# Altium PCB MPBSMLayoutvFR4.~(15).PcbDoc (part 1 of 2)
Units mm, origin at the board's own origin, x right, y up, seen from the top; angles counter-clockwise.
Board outline 131.7 x 110.39 mm, 4 copper layers (Top Layer, Power, GroundPlane, Bottom Layer), stack 2.286 mm thick; 156 components, 77 nets, 429 pads, 117 vias.
Unrouted connection lines stored in the file: 44.
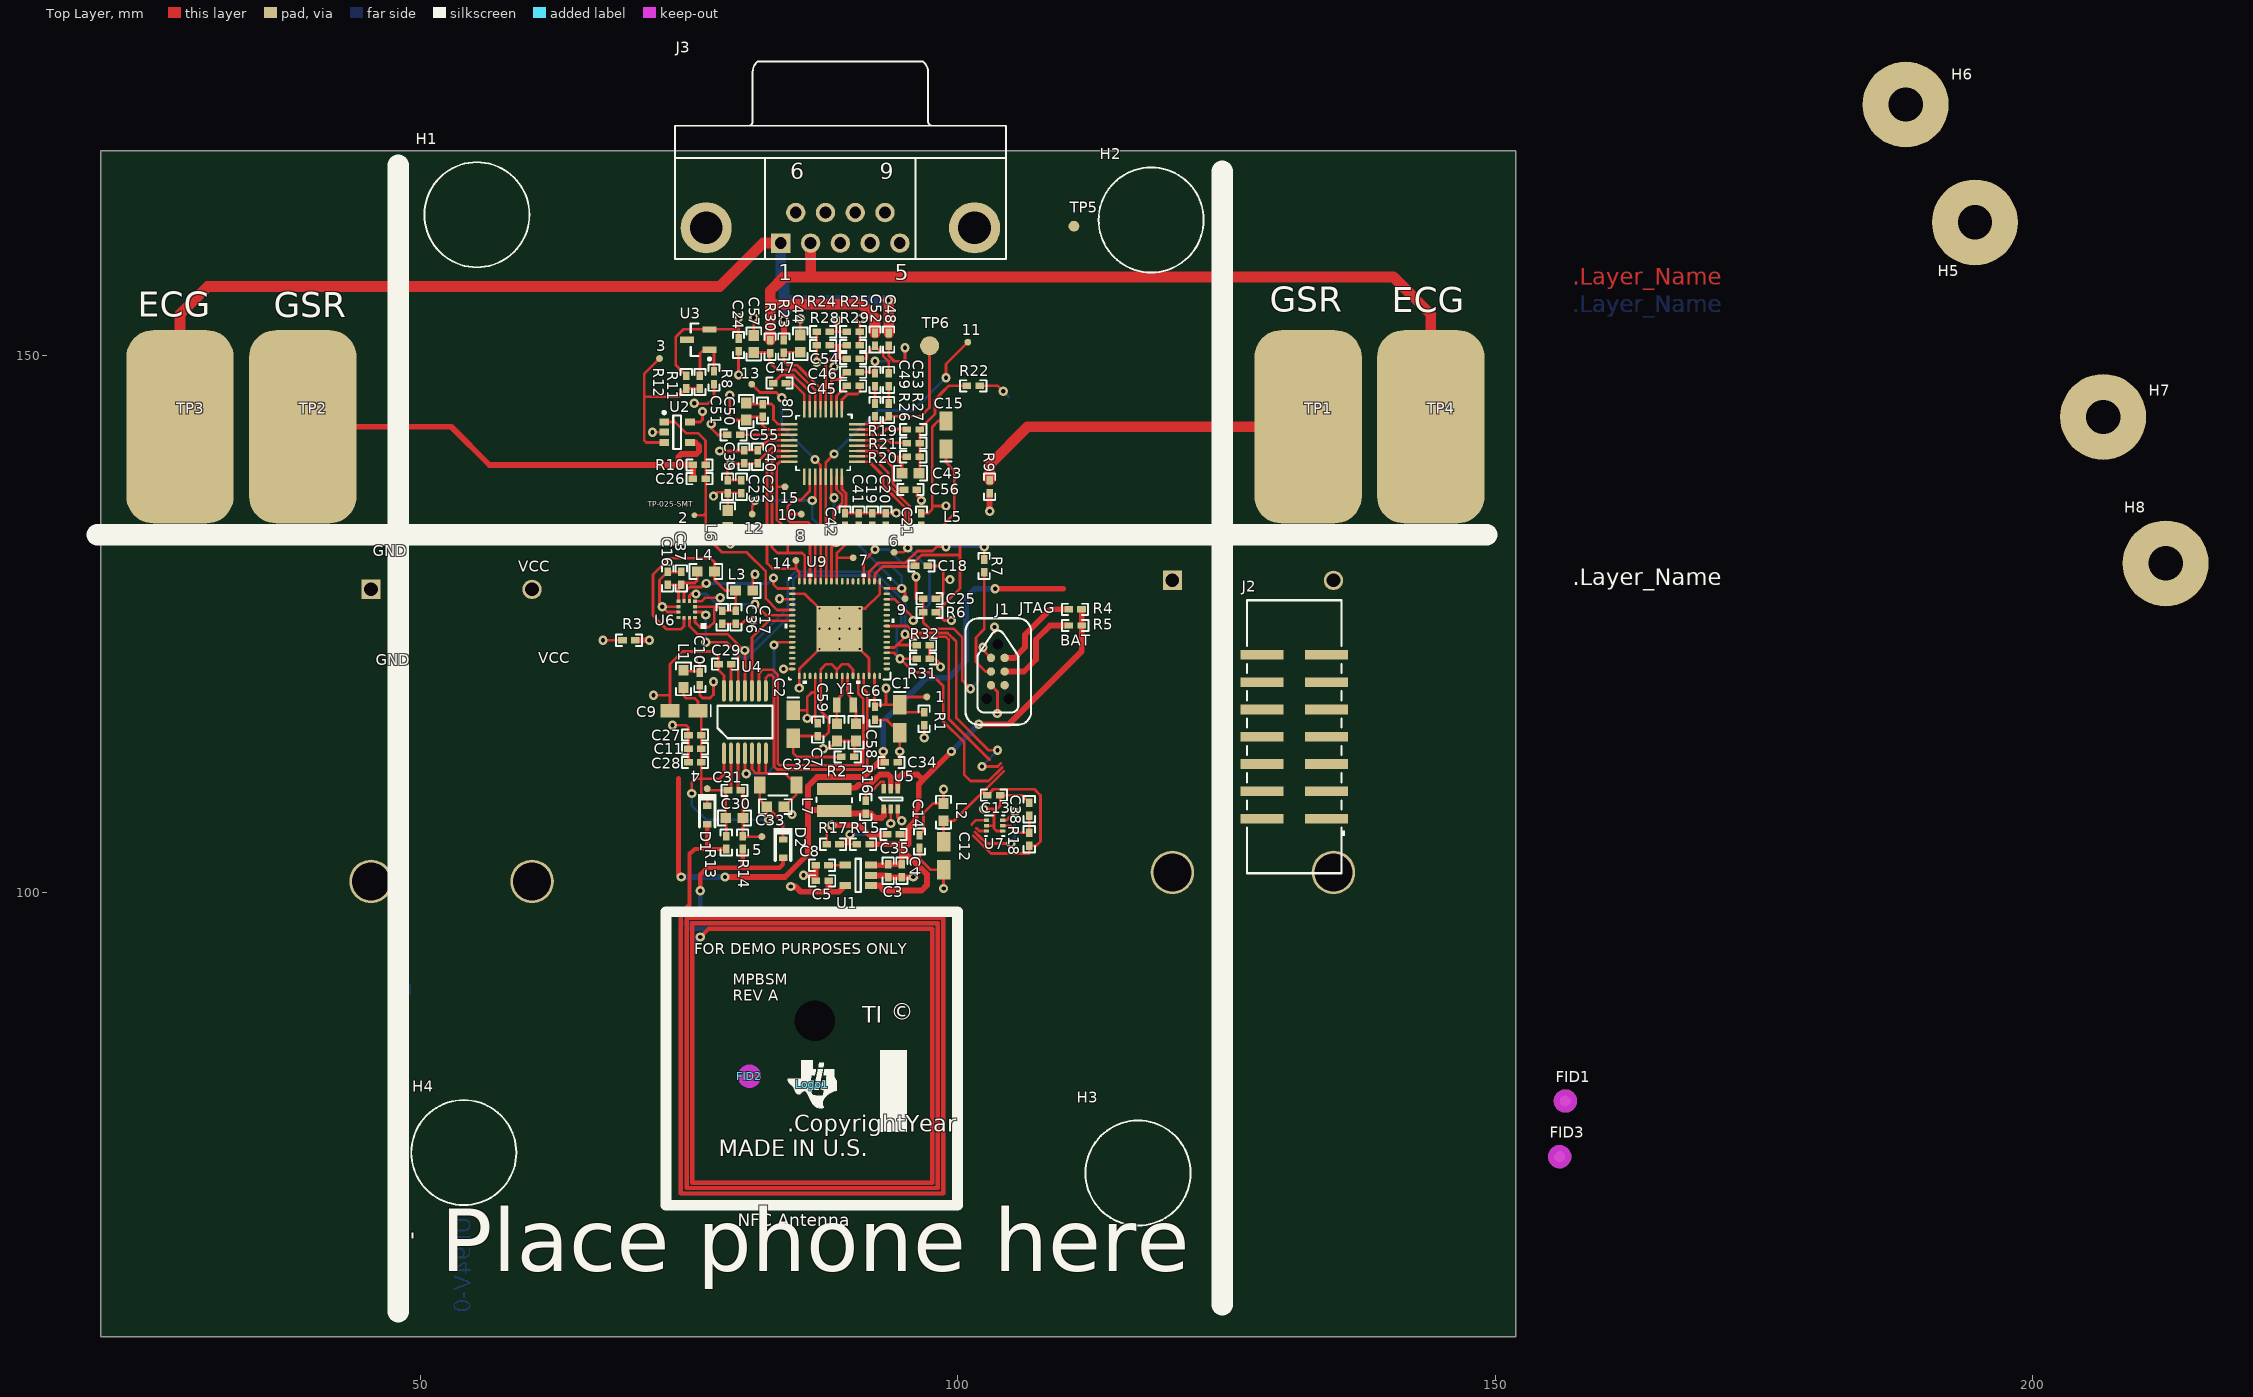
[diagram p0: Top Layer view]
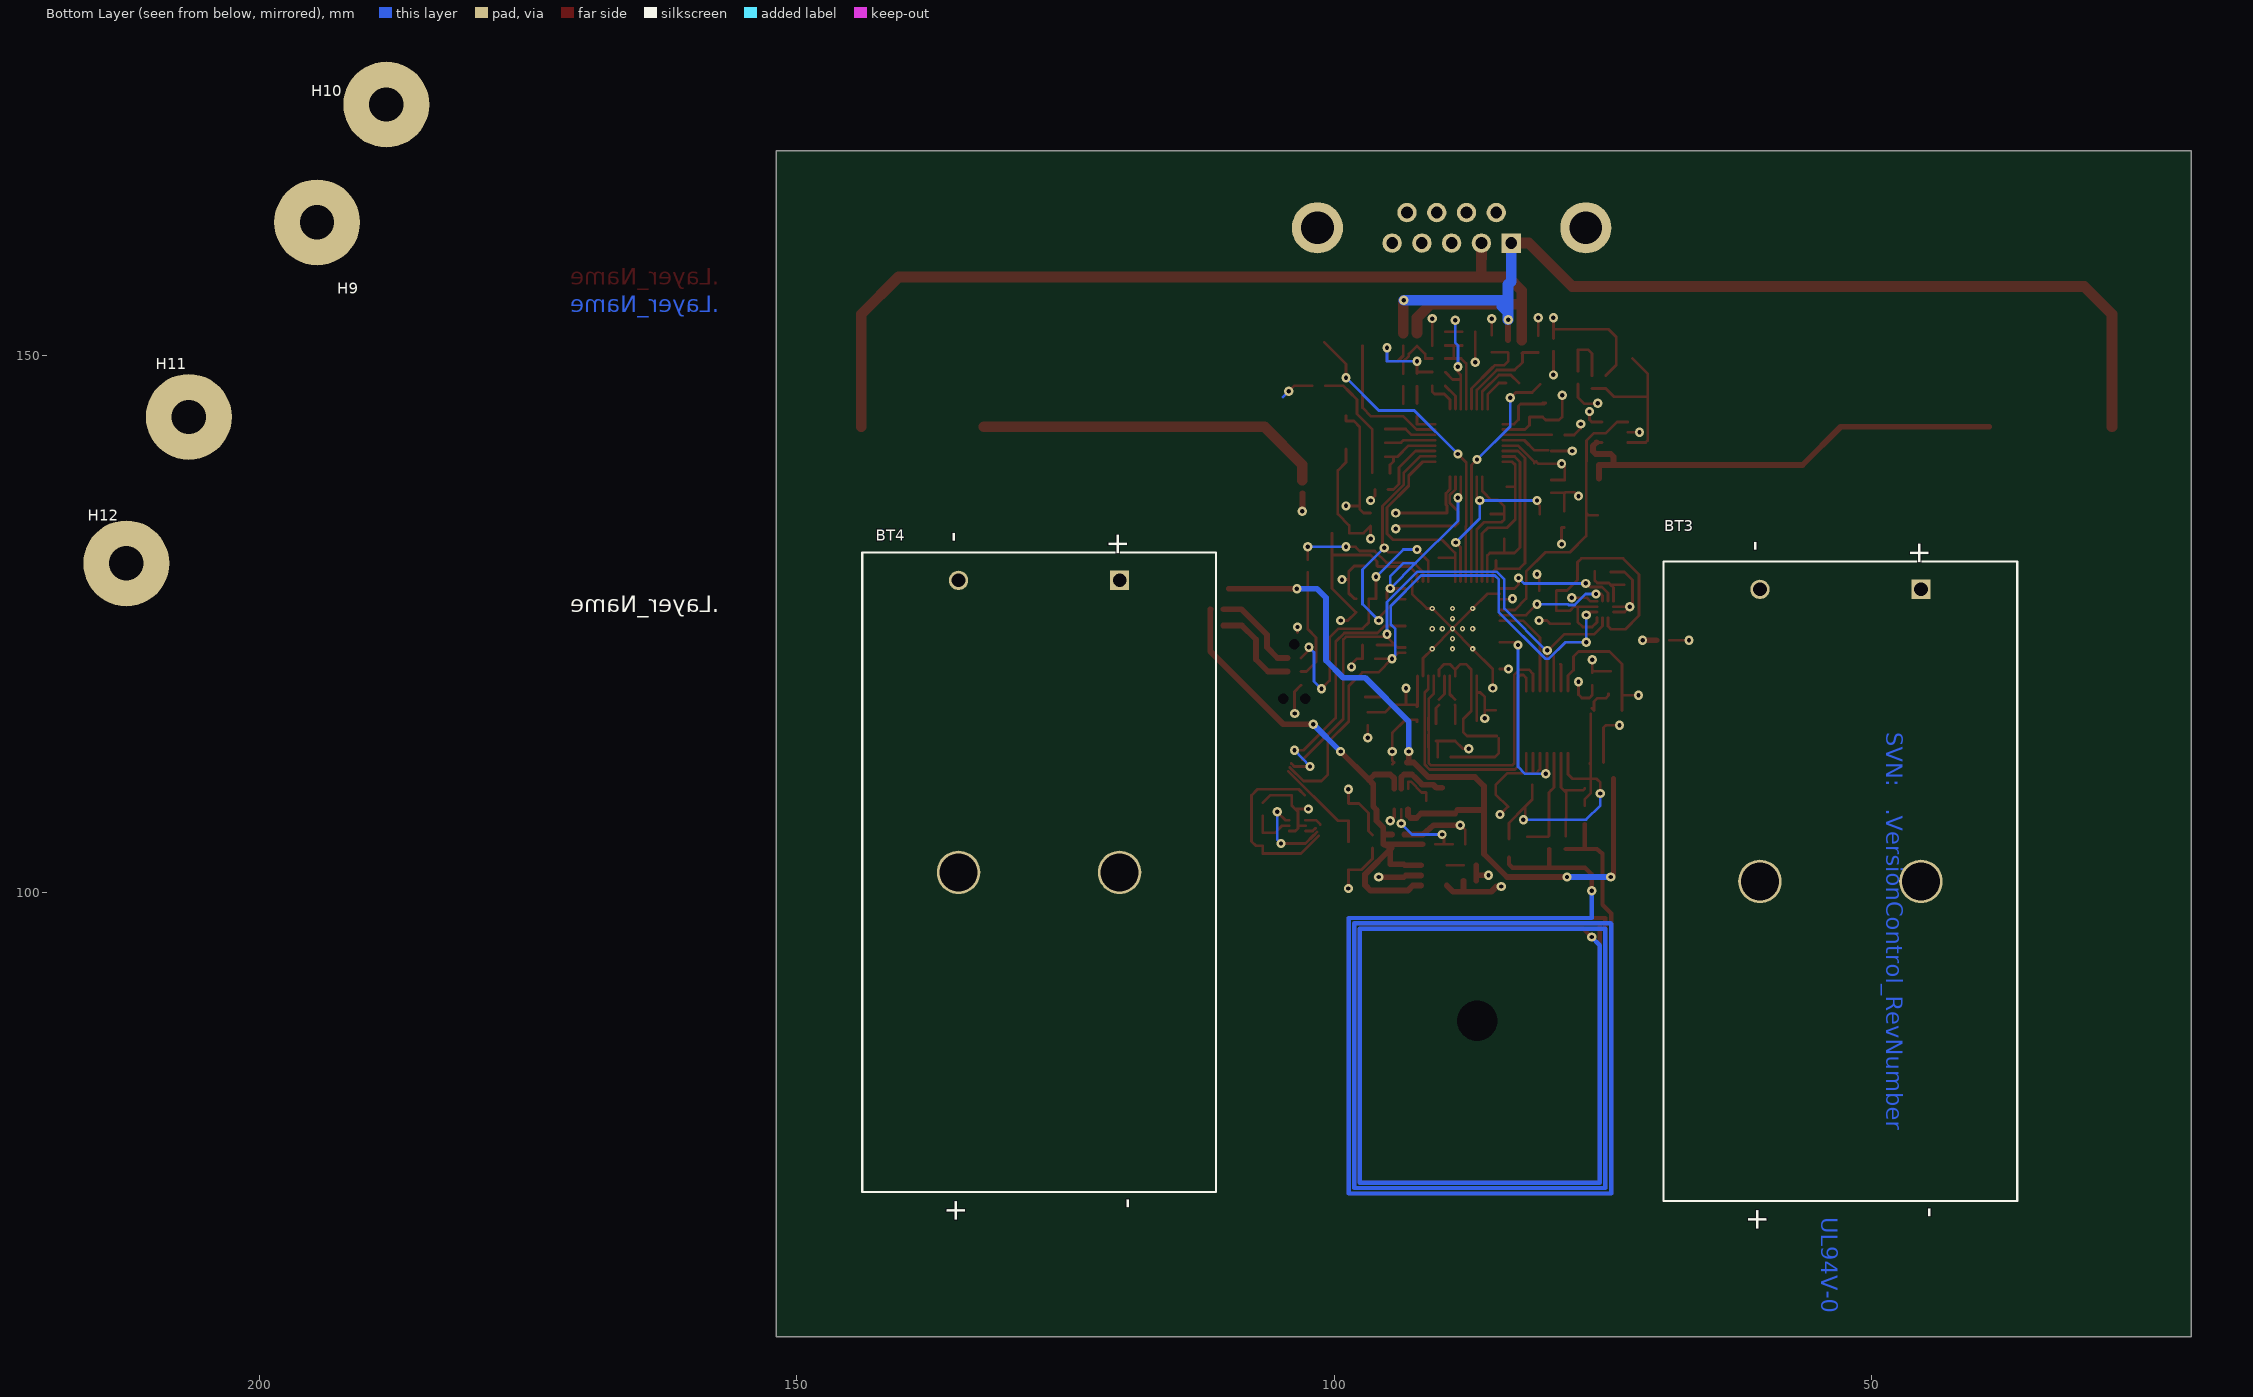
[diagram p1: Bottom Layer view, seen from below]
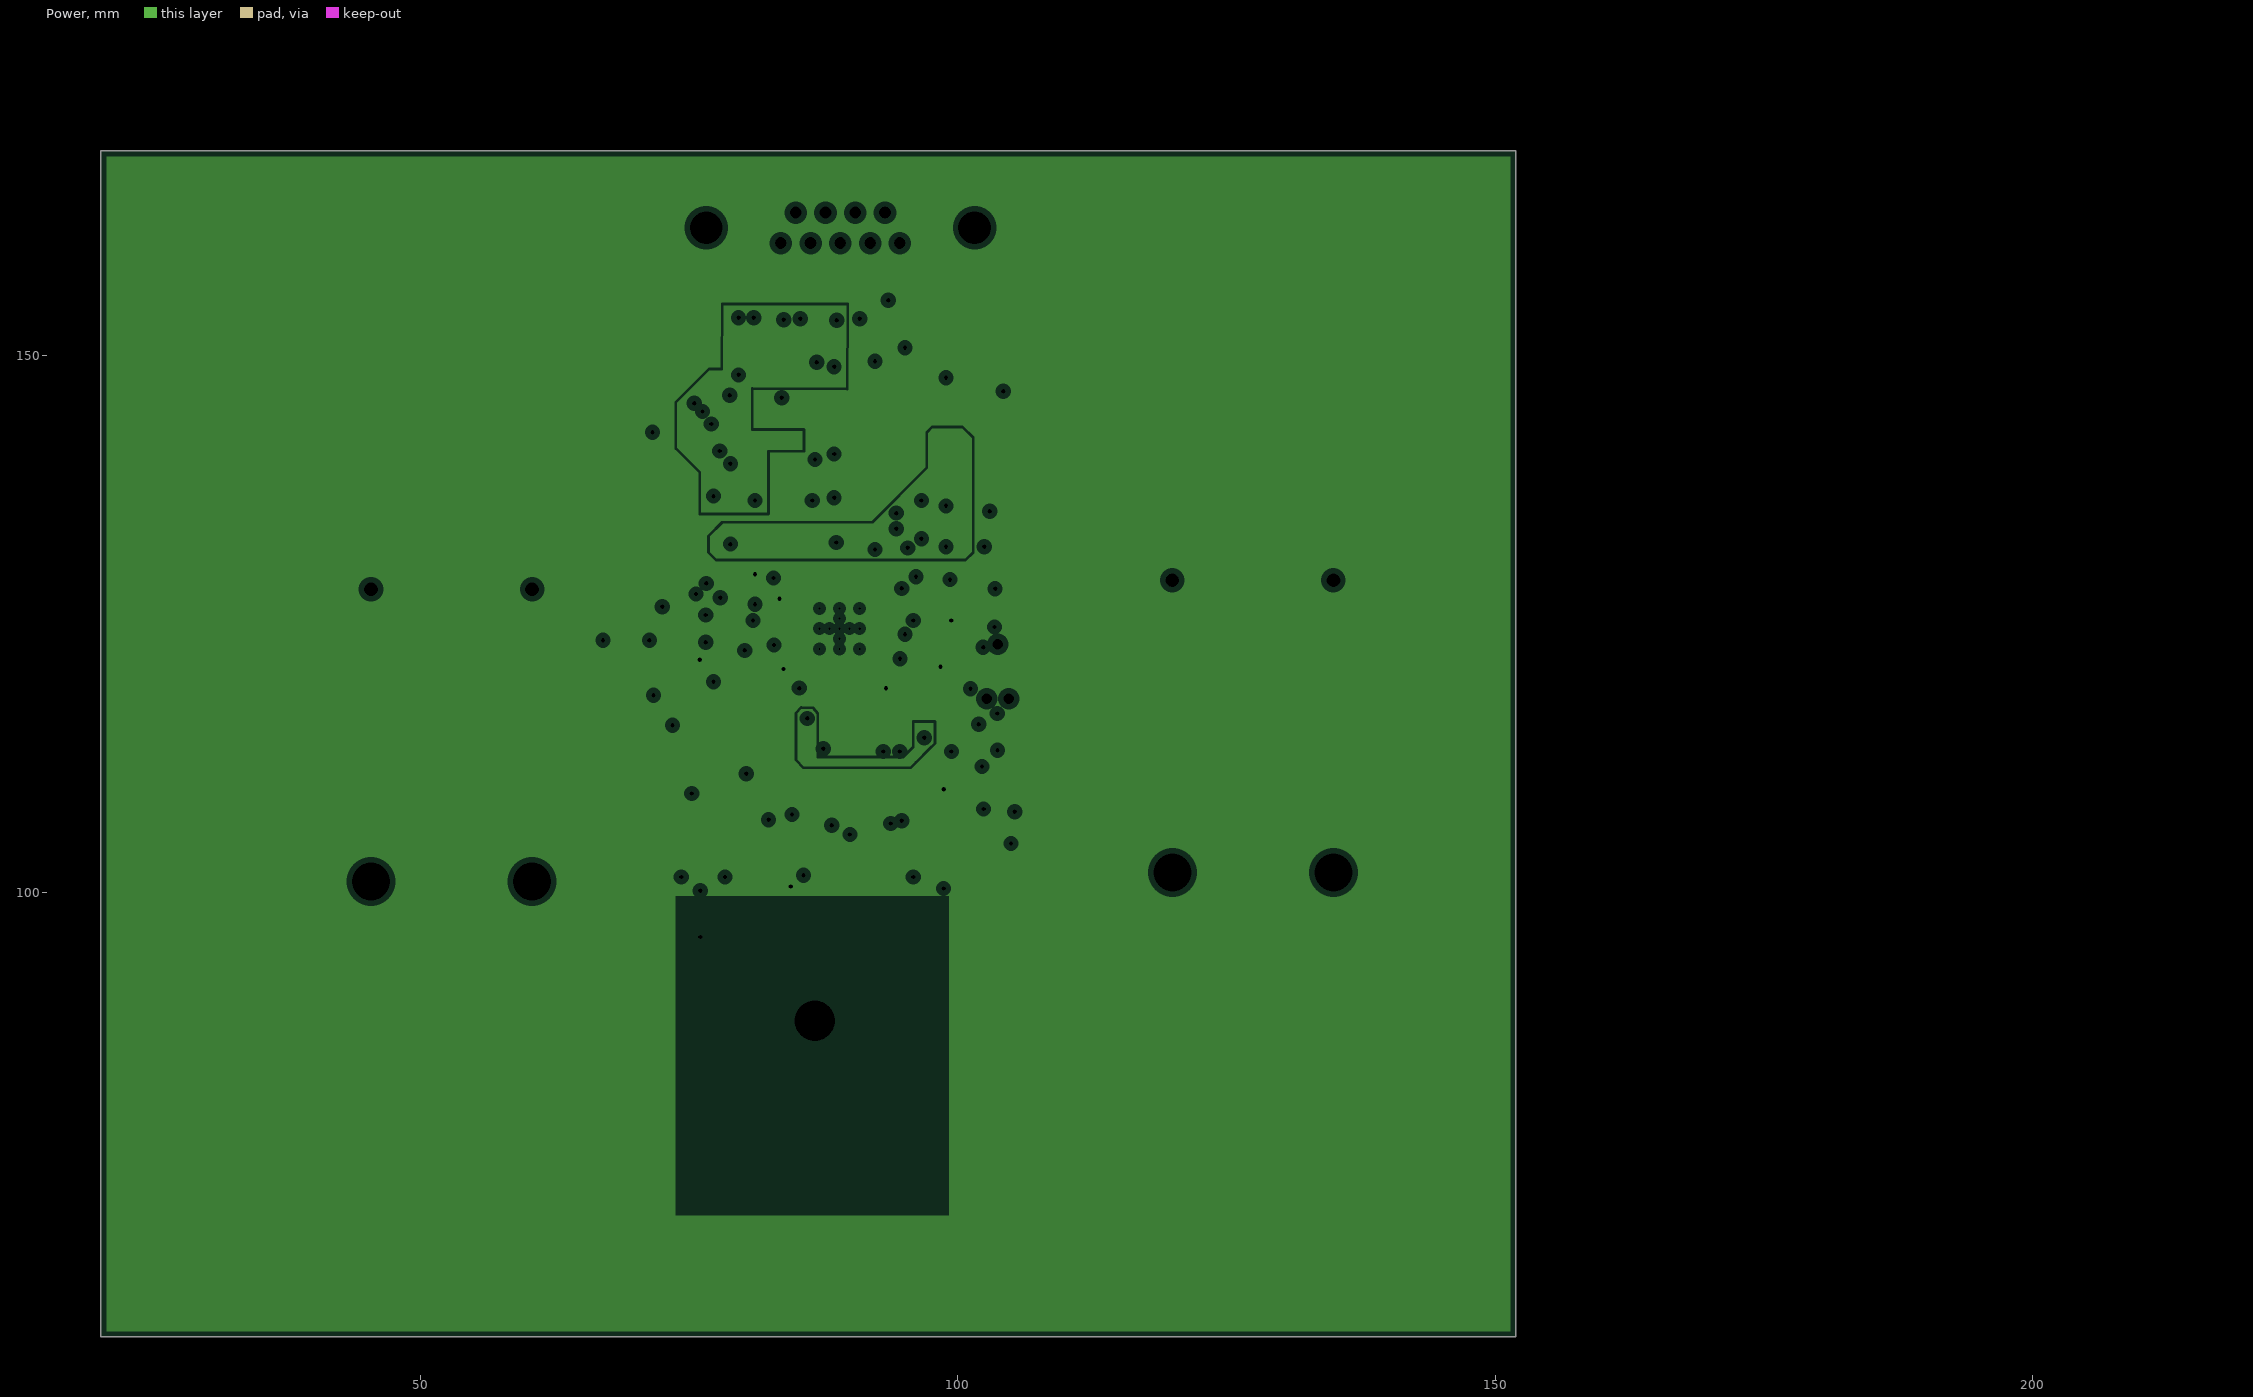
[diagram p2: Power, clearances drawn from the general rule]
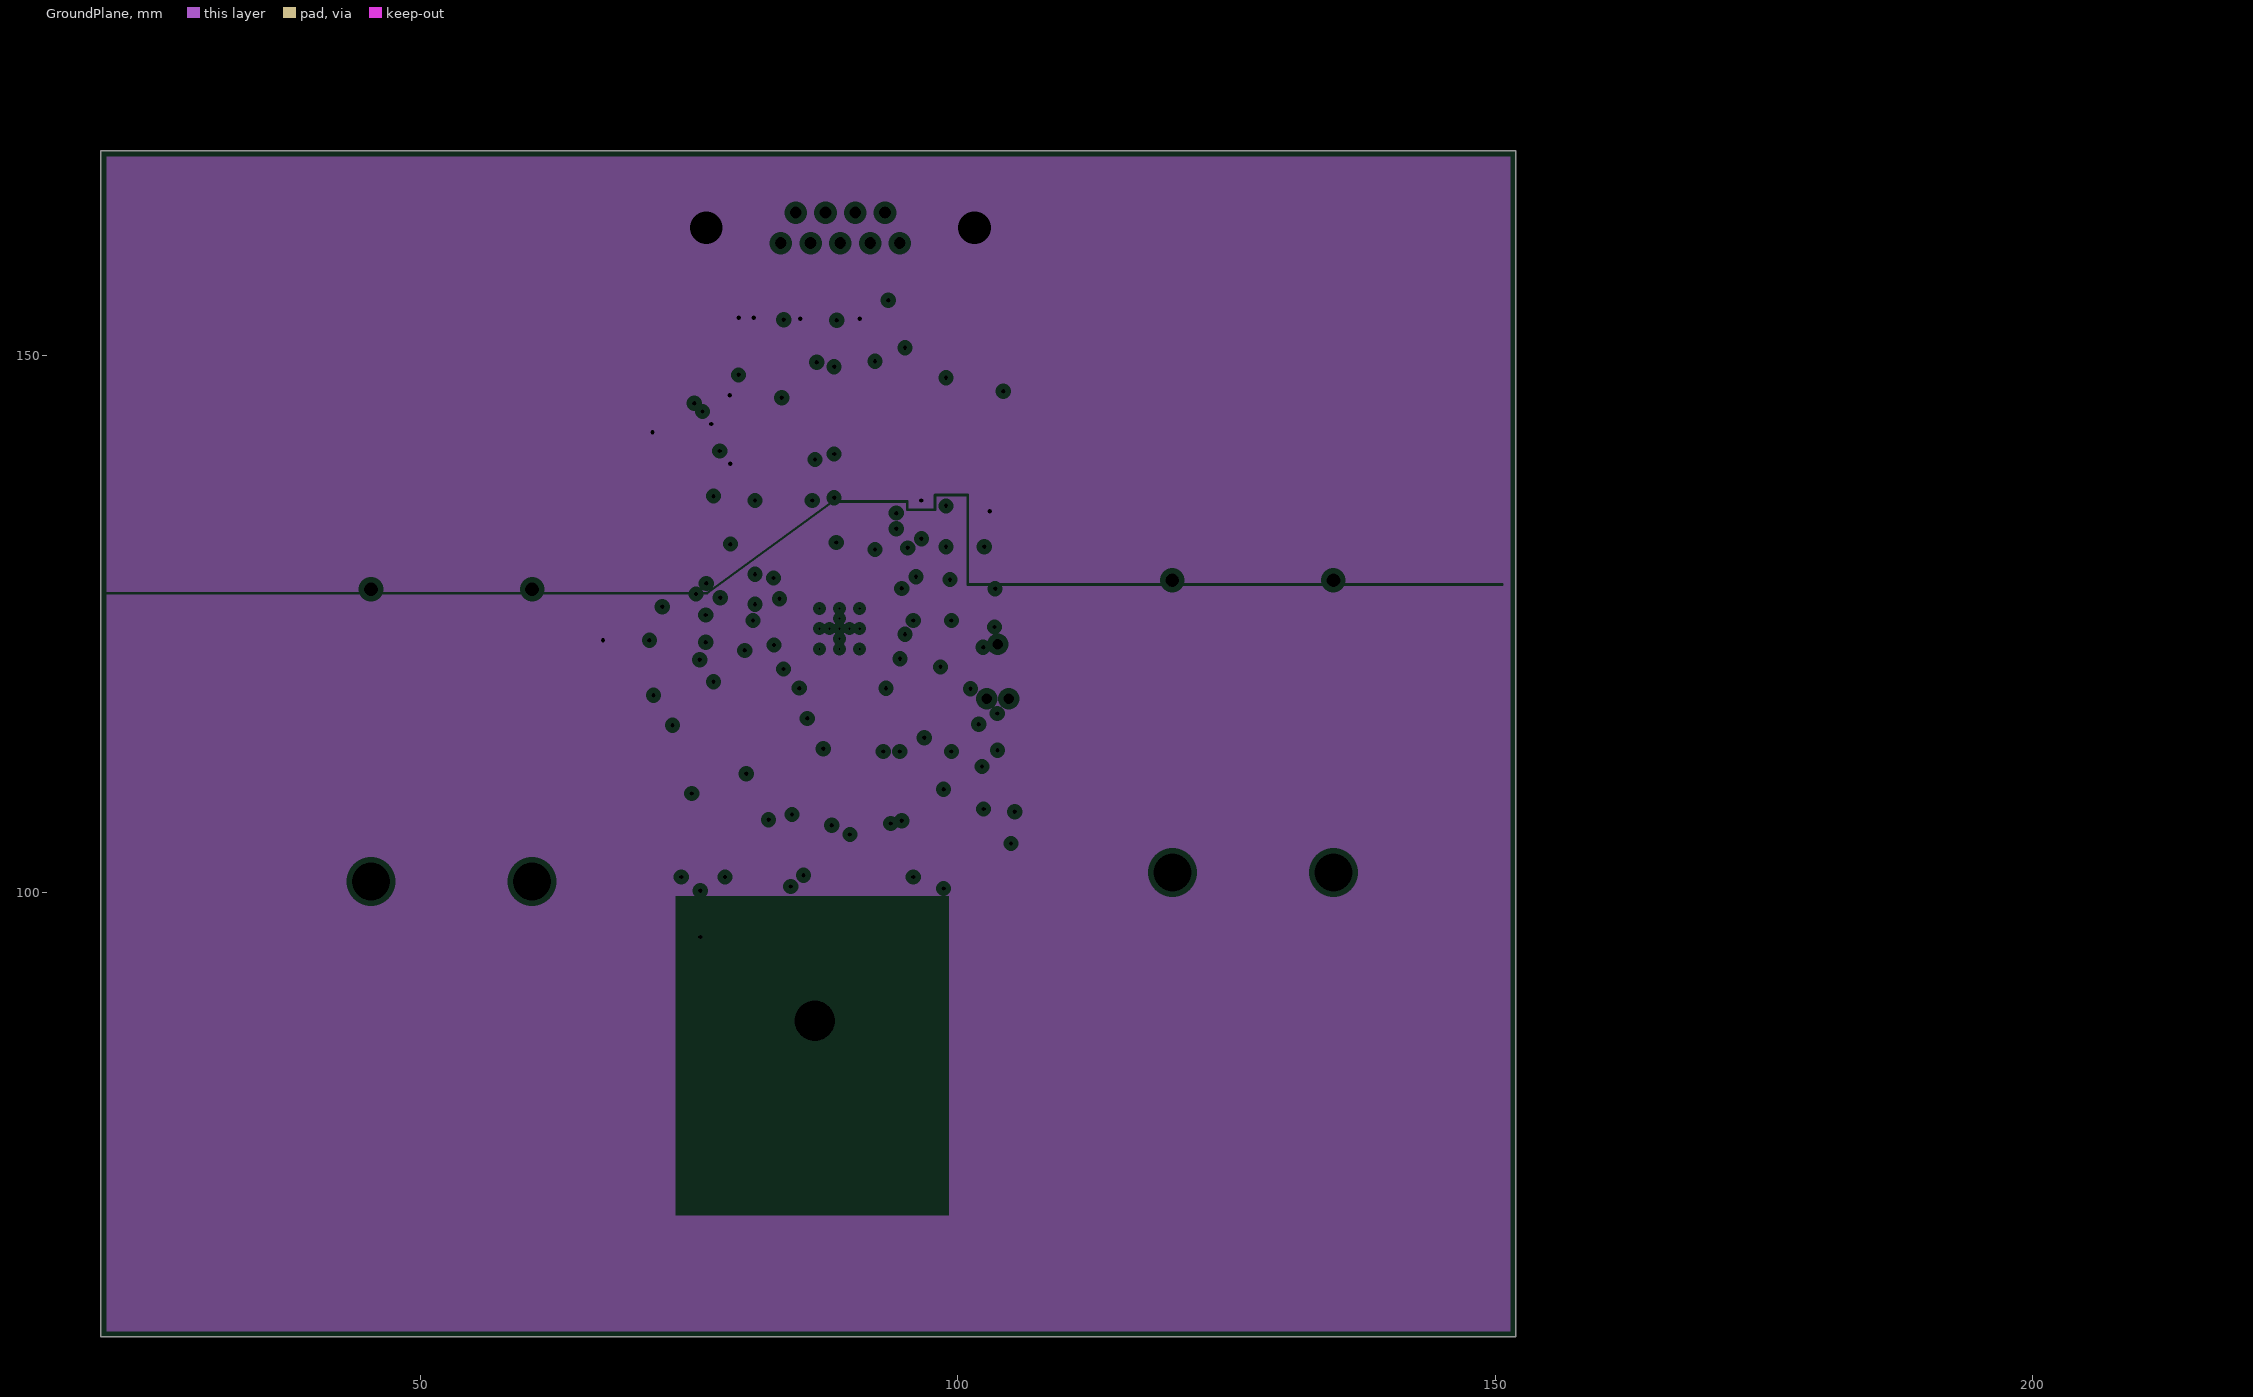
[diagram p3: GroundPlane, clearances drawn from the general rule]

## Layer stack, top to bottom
Top Solder: solder mask 0.0102, Solder Resist, Dk 3.5
Top Layer: signal copper 0.0356
Dielectric1: core 1.5037, FR-4, Dk 4.8
Power: plane copper 0.0356, net DVCC
Dielectric2: prepreg 0.32, FR-4, Dk 4.8
GroundPlane: plane copper 0.0356, net GND
Dielectric3: core 0.32, FR-4, Dk 4.8
Bottom Layer: signal copper 0.0356
Bottom Solder: solder mask 0.0102, Solder Resist, Dk 3.5

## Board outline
20.218,169.037 20.218,58.649 150.825,58.649 151.917,58.649 151.917,158.471 151.917,169.037 20.218,169.037

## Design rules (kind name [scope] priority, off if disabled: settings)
AcuteAngle [All] p1: minimum=4.50000000000000E+0001 checktracksonly=FALSE
AssemblyTestPointUsage [All] p1: valid=2
Clearance Clearance_BoardEdge_MountingHoles [OnCopper and InComponentClass('Mounting Holes') vs IsKeepOut] p1: gap=1.016
Clearance Clearance_BoardEdge_Poly [OnCopper and InPoly vs IsKeepOut] p2: gap=0.635
Clearance Clearance_BoardEdge [OnCopper and Not InComponentClass('Logo') and not InComponentClass('FiducialMark') and not InRegion(1000,500,4000,800) and Not IsKeepout vs IsKeepOut] p3: gap=1.905
Clearance Clearance_Poly [InPolygon] p4: gap=0.635
Clearance [All] p5: gap=0.1
ComponentClearance ComponentClearance_Shunt [InComponentClass('Header') vs InComponentClass('Shunt')] p1: gap=0 collisioncheckmode=3 verticalgap=0 showdistances=FALSE
ComponentClearance ComponentClearance_MountingHoles_FiducialMarks [InComponentClass('Mounting Holes') vs InComponentClass('FiducialMark')] p2: gap=1.27 collisioncheckmode=3 verticalgap=0.254 showdistances=FALSE
ComponentClearance ComponentClearance_Logo [InComponentClass('Logo')] p3: gap=1.27 collisioncheckmode=3 verticalgap=0.254 showdistances=FALSE
ComponentClearance ComponentClearance_ScrewToNut [(HasFootprint('NY PMS 440 0025 PH')) vs (HasFootprint('Keystone_1902C'))] p4: gap=0.127 collisioncheckmode=3 verticalgap=0.254 showdistances=FALSE
ComponentClearance ComponentClearance_MountingHoles [InComponentClass('Mounting Holes')] p5: gap=6.35 collisioncheckmode=3 verticalgap=2540 showdistances=FALSE
ComponentClearance ComponentClearance_SmallPassives [HasFootprint('0201*') or HasFootprint('0402*') or HasFootprint('0508') or HasFootprint('0603*') or HasFootprint('0612') or HasFootprint('0805*') or HasFootprint('0815*') or HasFootprint('0830*') or HasFootprint('1206*') or HasFootprint('1210*') or HasFootprint('1808*') or HasFootprint('1812*') or HasFootprint('1825*') or HasFootprint('2010*') or HasFootprint('2220*') or HasFootprint('2225*') or HasFootprint('2512*') or HasFootprint('2728*') or HasFootprint('3518*') vs HasFootprint('0201*') or HasFootprint('0402*') or HasFootprint('0508') or HasFootprint('0603*') or HasFootprint('0612') or HasFootprint('0805*') or HasFootprint('0815*') or HasFootprint('0830*') or HasFootprint('1206*') or HasFootprint('1210*') or HasFootprint('1808*') or HasFootprint('1812*') or HasFootprint('1825*') or HasFootprint('2010*') or HasFootprint('2220*') or HasFootprint('2225*') or HasFootprint('2512*') or HasFootprint('2728*') or HasFootprint('3518*')] p6: gap=0.508 collisioncheckmode=3 verticalgap=0.254 showdistances=FALSE
ComponentClearance ComponentClearance_THtoSMT [IsThruComponent vs IsSMTComponent] p7: gap=2.54 collisioncheckmode=3 verticalgap=0.762 showdistances=FALSE
ComponentClearance ComponentClearance_THtoTH [IsThruComponent vs IsThruComponent] p8: gap=3 collisioncheckmode=3 verticalgap=0.762 showdistances=FALSE
ComponentClearance [All] p9: gap=1.016 collisioncheckmode=3 verticalgap=0.254 showdistances=FALSE
DiffPairsRouting [All] p1: maxlimit=2.54 minlimit=0.254 mostfreqgap=0.254 toplayer_minwidth=0.381 toplayer_maxwidth=0.381 toplayer_prefwidth=0.381 bottomlayer_minwidth=0.381 bottomlayer_maxwidth=0.381 bottomlayer_prefwidth=0.381 maxuncoupledlength=25.4
FabricationTestPointUsage TestPointUsage [All] p1: valid=2 allowmultiple=FALSE
FabricationTestpoint Testpoint [All] p1: side=3 testpointundercomponent=TRUE minsize=1.016 maxsize=2.54 preferedsize=1.524 minholesize=0 maxholesize=1.016 preferedholesize=0.813 testpointgrid=0.025 allowsidetop=TRUE allowsidebottom=TRUE usegrid=TRUE gridtolerance=0
FanoutControl Fanout_LCC [IsLCC] p1: bgadir=Out bgaviamode=Centered fanoutstyle=Auto fanoutdirection=Alternating viagrid=0.025 // Fanout_LCC (Default Rule)
FanoutControl Fanout_BGA [IsBGA] p2: bgadir=Out bgaviamode=Centered fanoutstyle=Auto fanoutdirection=Alternating viagrid=0.025 // Fanout_BGA (Default Rule)
FanoutControl Fanout_Default [All] p4: bgadir=Out bgaviamode=Centered fanoutstyle=Auto fanoutdirection=Alternating viagrid=0.025 // Fanout_Default (Default Rule)
FanoutControl Fanout_Small [(CompPinCount < 5)] p5: bgadir=Out bgaviamode=Centered fanoutstyle=Auto fanoutdirection=OutThenIn viagrid=0.025 // Fanout_Small (Default Rule)
Height [All] p1: minheight=0 maxheight=55.4 prefheight=12.7
HoleSize [All] p1: absolutevalues=TRUE maxlimit=6.375 minlimit=0.1 maxpercent=80.000 minpercent=20.000
MinimumAnnularRing MinimumAnnularRing_ThermalPadVias [IsVia and InAnyComponent] p1: minimumring=0.15
MinimumAnnularRing [All] p2: minimumring=0.229
MinimumSolderMaskSliver MinimumSolderMaskSliver_Logo [InComponentClass('Logo') vs InComponentClass('Logo')] p1: minsoldermaskwidth=0.018
MinimumSolderMaskSliver [All] p2: minsoldermaskwidth=0.08
PlaneClearance [All] p1: clearance=0.508
PlaneConnect [All] p1: planeconnectstyle=Relief reliefexpansion=0.254 reliefentries=4 reliefconductorwidth=0.254 reliefairgap=0.254
PolygonConnect [All] p1: connectstyle=Relief reliefconductorwidth=0.254 reliefentries=4 polygonreliefangle="90 Angle" airgapwidth=0.254
RoutingVias ThermalPadVias [IsVia and InAnyComponent] p1: holewidth=0.2 width=0.5 viastyle="Through Hole" minholewidth=0.2 minwidth=0.5 maxholewidth=0.33 maxwidth=0.6
RoutingVias [All] p2: holewidth=0.406 width=0.864 viastyle="Through Hole" minholewidth=0.2 minwidth=0.66 maxholewidth=1.016 maxwidth=1.651
SMDToCorner [All] p1: distance=30000
SilkToSilkClearance SilkToSilkClearance_Pb-FreeLogo [(HasFootprint('Pb-Free_Overlay_Medium') OR HasFootprint('Pb-Free_Overlay_Small')) vs (HasFootprint('Pb-Free_Overlay_Medium') OR HasFootprint('Pb-Free_Overlay_Small'))] p1: silktosilkclearance=0
SilkToSilkClearance [All] p2: silktosilkclearance=0
SilkToSolderMaskClearance SilkscreenOverComponentPads [IsPad] p1: minsilkscreentomaskgap=0.127 clearancetoexposedcopper=TRUE
SolderMaskExpansion [All] p1: expansion=0.05
Width [All] p1: maxlimit=2.54 minlimit=0.152 preferedwidth=0.254 checkconnectedcopper=TRUE
14 further rules are at their usual default settings.

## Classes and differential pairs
component class Logo: Logo1
component class Designator: FID1 FID2 FID3 H1 H2 H3 H4 H5 H6 H7 H8 H9 H10 H11 H12 Logo1 ZZ1 ZZ2 ZZ3 ZZ4
component class FiducialMark: FID1 FID2 FID3
component class AssemblyNote: ZZ1 ZZ2 ZZ3 ZZ4
component class Battery: BT3 BT4 U?
component class BMA280: C36 C37 U6
component class "Boost Converter": C34 C35 L7 R15 R16 R17 U5
component class ECG: 6 7 8 9 10 11 12 13 14 15 C39 C40 C41 C42 C43 C44 C45 C46 C47 C48 C49 C50 C51 C52 C53 C54 C55 C56 C57 R19 R20 R21 R22 R23 R24 R25 R26 R27 R28 R29 R30 TP6 U8
component class GSR: 2 3 C26 R8 R9 R10 R11 R12 U2 U3
component class "JTAG SPY-BY-WIRE": C25 J1 J2 R4 R5 R6 R7
component class MSP430FR5XXX: C58 C59 R31 R32 U9 Y1
component class "Power Filtering": 1 C1 C2 C3 C4 C5 C6 C7 C8 C9 C10 C11 C12 C13 C14 C15 C16 C17 C18 C19 C20 C21 C22 C23 C24 L1 L2 L3 L4 L5 L6 R1 R2 R3 U1
component class Temperature: C38 R18 U7
component class Transponder: 4 5 C27 C28 C29 C30 C31 C32 C33 D1 D2 R13 R14 U4
component class "Analog Connector": J3
component class "Mounting Holes": H5 H6 H7 H8

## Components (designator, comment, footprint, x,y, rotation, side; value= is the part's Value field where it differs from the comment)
1 "TP-025-SMT" TP_25MIL-SMT#1 97.104,118.212 r90 top
2 "TP-025-SMT" TP_25MIL-SMT#2 75.463,135.128 r0 top
3 "TP-025-SMT" TP_25MIL-SMT#1 72.212,149.708 r0 top
4 "TP-025-SMT" TP_25MIL-SMT#1 76.653,109.676 r0 top
5 "TP-025-SMT" TP_25MIL-SMT#1 81.737,105.207 r270 top
6 "TP-025-SMT" TP_25MIL-SMT#1 94.056,131.674 r0 top
7 "TP-025-SMT" TP_25MIL-SMT#1 90.246,131.166 r0 top
8 "TP-025-SMT" TP_25MIL-SMT#1 84.15,133.198 r0 top
9 "TP-025-SMT" TP_25MIL-SMT#1 95.072,127.356 r0 top
10 "TP-025-SMT" TP_25MIL-SMT#1 85.42,135.23 r0 top
11 "TP-025-SMT" TP_25MIL-SMT#1 100.914,151.232 r0 top
12 "TP-025-SMT" TP_25MIL-SMT#1 80.848,135.23 r0 top
13 "TP-025-SMT" TP_25MIL-SMT#1 80.797,147.32 r0 top
14 "TP-025-SMT" TP_25MIL-SMT#1 84.912,130.912 r90 top
15 "TP-025-SMT" TP_25MIL-SMT#1 83.896,137.77 r0 top
BT3 "2462" Keystone_2462 52.857,114.63 r270 bottom
BT4 "2462" Keystone_2462 127.457,115.468 r270 bottom
C1 "293D106X9010A2TE3" 3216-18 94.564,116.18 r270 top
C2 "293D106X9010A2TE3" 3216-18 84.658,115.672 r270 top
C3 "C1005X5R1A104K" 0402 93.502,102.028 r270 top
C4 "C1005X5R0J105M" 0402 94.772,102.028 r270 top
C5 "C1005X5R1C225K050BC" 0402 87.355,101.092 r180 top
C6 "C1005X5R1A104K" 0402 92.278,116.688 r270 top
C7 "C1005X5R1A104K" 0402 86.944,115.164 r270 top
C8 "C1005X7R1E103K" 0402 87.351,102.54 r180 top
C9 "293D105X9016A2TE3" 3216-18 74.498,116.942 r180 top
C10 "C1005X5R1A104K" 0402 75.971,119.888 r270 top
C11 "C1005X5R1A104K" 0402 75.514,113.386 r180 top
C12 "293D106X9010A2TE3" 3216-18 98.661,103.422 r270 top
C13 "C1005X5R1A104K" 0402 103.337,109.068 r0 top
C14 "C1005X5R1A104K" 0402 96.421,104.75 r270 top
C15 "293D105X9016A2TE3" 3216-18 98.882,142.596 r90 top
C16 "CL05A106MQ5NUNC" 0402 72.974,129.247 r90 top
C17 "CL05A106MQ5NUNC" 0402 79.324,125.624 r270 top
C18 "C1005X5R1A104K" 0402 96.596,130.404 r0 top
C19 "C1005X5R1A104K" 0402 92.024,134.722 r90 top
C20 "C1005X5R1C225K050BC" 0402 93.294,134.722 r90 top
C21 "CL05A106MQ5NUNC" 0402 96.596,134.722 r90 top
C22 "CL05A106MQ5NUNC" 0402 79.832,137.77 r90 top
C23 "C1005X5R1A104K" 0402 78.562,137.77 r90 top
C24 "C1005X5R1A104K" 0402 79.578,150.978 r90 top
C25 "C1005X8R1H222K" 0402 97.358,127.356 r0 top
C26 "C1005X7R1E103K" 0402 75.93,138.532 r180 top
C27 "C1005X5R0J105M" 0402 75.514,114.656 r180 top
C28 "C1005X5R1A104K" 0402 75.514,112.116 r180 top
C29 "GRM155R60J474KE19D" 0402 78.308,121.26 r0 top
C30 "C1608C0G1H330J" 0603 79.193,106.941 r0 top
C31 "GRM1555C1H390JA01D" 0402 79.193,109.515 r0 top
C32 "C3216X5R1A107M160AC" 1206_190 83.257,110.023 r0 top
C33 "Used in BOM report" 0603 83.003,107.991 r0 top
C34 "CL05A106MQ5NUNC" 0402 93.802,112.116 r0 top
C35 "CL05A106MQ5NUNC" 0402 94.005,105.41 r180 top
C36 "C1005X5R1A104K" 0402 78.054,125.624 r270 top
C37 "C1005X5R1A104K" 0402 74.244,129.247 r90 top
C38 "C1005X7R1E103K" 0402 106.639,107.752 r90 top
C39 "C1005X5R1C105K050BC" 0402 80.086,140.564 r270 top
C40 "C1005X5R1A104K" 0402 81.356,140.564 r270 top
C41 "C1005X5R1C105K050BC" 0402 90.754,134.722 r90 top
C42 "C1005X5R1A104K" 0402 89.484,134.722 r90 top
C43 "C0603C152K5RACTU" 0603 95.58,139.04 r180 top
C44 "GRM1885C1H302JA01D" 0603 85.319,151.091 r90 top
C45 "GRM155R61A472KA01D" 0402 90.246,147.168 r0 top
C46 "C1005X8R1H222K" 0402 90.246,148.438 r0 top
C47 "GRM155R61A472KA01D" 0402 83.388,147.422 r180 top
C48 "C1005X5R1A104K" 0402 93.548,151.486 r270 top
C49 "C1005X8R1H222K" 0402 92.278,147.722 r90 top
C50 "C1005X5R1A104K" 0402 81.813,144.872 r270 top
C51 "C1608X5R0J106M" 0603 80.289,144.78 r270 top
C52 "C1005X5R1A104K" 0402 92.278,151.486 r270 top
C53 "C1005X8R1H222K" 0402 93.548,147.722 r90 top
C54 "C1005X8R1H222K" 0402 90.246,149.708 r0 top
C55 "C1005X5R1C105K050BC" 0402 79.116,142.596 r180 top
C56 "C1005X5R1C105K050BC" 0402 95.58,137.516 r0 top
C57 "GRM1885C1H302JA01D" 0603 80.997,151.063 r90 top
C58 "06035A100JAT2A" 0603 90.5,114.91 r270 top
C59 "06035A100JAT2A" 0603 88.748,114.91 r270 top
D1 "CDBU0130L" SOD-523F 76.653,107.229 r270 top
D2 "CDBU0130L" SOD-523F 83.718,104.089 r270 top
FID1 "Fiducial" Fiducial10-20 156.54,80.594 r0 top
FID2 "Fiducial" Fiducial10-20 80.594,82.906 r0 top
FID3 "Fiducial" Fiducial10-20 156.007,75.413 r0 top
H1 "SJ61A2" Bumpon_SJ61A2 55.22,163.093 r0 top
H2 "SJ61A2" Bumpon_SJ61A2 117.983,162.611 r0 top
H3 "SJ61A2" Bumpon_SJ61A2 116.764,73.889 r0 top
H4 "SJ61A2" Bumpon_SJ61A2 54,75.794 r0 top
H5 "NY PMS 440 0025 PH" "NY PMS 440 0025 PH" 194.666,162.382 r90 top
H6 "NY PMS 440 0025 PH" "NY PMS 440 0025 PH" 188.214,173.355 r90 top
H7 "NY PMS 440 0025 PH" "NY PMS 440 0025 PH" 206.604,144.272 r90 top
H8 "NY PMS 440 0025 PH" "NY PMS 440 0025 PH" 212.421,130.638 r90 top
H9 "1902C" Keystone_1902C 194.665,162.376 r90 bottom
H10 "1902C" Keystone_1902C 188.239,173.33 r90 bottom
H11 "1902C" Keystone_1902C 206.604,144.272 r90 bottom
H12 "1902C" Keystone_1902C 212.42,130.632 r180 bottom
J1 "TC2030-MCP-NL" TC2030-MCP-NL 103.708,120.574 r180 top
J2 "61201420621" Wurth_61201420621 131.293,114.503 r180 top
J3 "182-009-213R171" NORCOMP_182-009-213R171 89.052,171.374 r0 top
L1 "BLM18HG601SN1D" 0603 74.447,119.888 r270 top
L2 "BLM18HG601SN1D" 0603 98.661,107.486 r270 top
L3 "BLM18HG601SN1D" 0603 80.086,128.118 r180 top
L4 "BLM18HG601SN1D" 0603 76.53,129.896 r0 top
L5 "BLM18HG601SN1D" 0603 99.39,133.452 r180 top
L6 "BLM18HG601SN1D" 0603 78.562,134.772 r90 top
L7 "EPL3015-472MLB" EPL3015 88.494,108.61 r90 top
Logo1 "Texas Instruments" TI_Symbol_Overlay_Small 86.436,82.144 r0 top
R1 "ERJ-2GE0R00X" 0402 96.85,116.18 r270 top
R2 "ERJ-2GE0R00X" 0402 89.738,112.624 r180 top
R3 "ERJ-2GE0R00X" 0402 69.377,123.489 r180 top
R4 "ERJ-2GE0R00X" 0402 110.896,126.365 r0 top
R5 "ERJ-2GE0R00X" 0402 110.916,124.861 r0 top
R6 "CRCW040247K0JNED" 0402 97.358,126.086 r0 top
R7 "ERJ-2GE0R00X" 0402 102.438,130.404 r90 top
R8 "CRCW040221K5FKED" 0402 77.292,147.93 r270 top
R9 "CRCW040210K0FKED" 0402 102.946,137.77 r90 top
R10 "ERJ-2RKF1004X" 0402 75.93,139.802 r0 top
R11 "CRCW040211K8FKED" 0402 75.977,147.517 r90 top
R12 "CRCW04028K06FKED" 0402 74.707,147.517 r270 top
R13 "ERJ-2GE0R00X" 0402 78.431,104.655 r270 top
R14 "ERJ-2GE0R00X" 0402 79.955,104.655 r270 top
R15 "ERJ-2RKF1004X" 0402 91.17,104.496 r0 top
R16 "ERJ-2GE0R00X" 0402 91.415,107.95 r90 top
R17 "ERJ-2RKF2003X" 0402 88.376,104.496 r0 top
R18 "CRCW04024K99FKED" 0402 106.639,104.958 r270 top
R19 "ERJ-2GE0R00X" 0402 95.834,143.104 r0 top
R20 "ERJ-2RKF1004X" 0402 95.834,140.564 r0 top
R21 "ERJ-2RKF1003X" 0402 95.834,141.834 r0 top
R22 "ERJ-2RKF1003X" 0402 101.422,147.168 r0 top
R23 "CRCW040251K1FKED" 0402 83.795,150.837 r270 top
R24 "CRCW040210M0FKED" 0402 87.452,152.202 r180 top
R25 "CRCW040210M0FKED" 0402 90.246,152.202 r180 top
R26 "CRCW040240K2FKED" 0402 92.278,144.928 r270 top
R27 "CRCW040240K2FKED" 0402 93.548,144.928 r270 top
R28 "CRCW040210M0FKED" 0402 87.452,150.932 r180 top
R29 "CRCW040210M0FKED" 0402 90.246,150.932 r180 top
R30 "CRCW040251K1FKED" 0402 82.521,150.809 r270 top
R31 "CRCW04023K30JNED" 0402 96.758,121.768 r180 top
R32 "CRCW04023K30JNED" 0402 96.758,123.038 r180 top
TP1 "TESTPOINT" TP_SM_1MM#1 132.588,143.358 r0 top
TP2 "TESTPOINT" TP_SM_1MM#2 39.014,143.358 r90 top
TP3 "TESTPOINT" TP_SM_1MM#2 27.584,143.358 r90 top
TP4 "TESTPOINT" TP_SM_1MM#2 144.018,143.358 r90 top
TP5 "TESTPOINT" TP_SM_1MM#3 110.795,162.027 r90 top
TP6 "Pogo Pad" PogoPad 97.358,150.901 r0 top locked
U1 "TPS73030DBVR" DBV0005A_N 90.703,101.6 r180 top
U2 "LMP2231AMFE" MF05A_L 73.852,142.85 r0 top
U3 "LM4041AIM3-1.2" MF03A_N 75.819,151.46 r180 top
U4 "RF430CL331HCPW" PW0014A_M 80.169,115.864 r90 top
U5 "TPS61220DCK" DCK0006A_N 93.751,108.712 r90 top
U6 "BMA280" LGA-12P 74.752,126.361 r90 top
U7 "TMP112AIDRL" DRL0006A 103.411,106.221 r0 top
U8 "ADS1292RIPBS" PBS0032A_N 87.452,141.853 r270 top
U9 "MSP430FR5889IRGCR" RGC0064B 88.976,124.562 r180 top
Y1 "FC-12M 32.7680KA-A3" Epson_FC-12M 89.484,117.45 r0 top
ZZ1 "This Assembly Note is for PCB labels only" AssemblyNoteLabel 35.992,195.631 r0 top
ZZ2 "These assemblies are ESD sensitive, ESD precautions shall be observed." AssemblyNote 35.992,192.865 r0 top
ZZ3 "These assemblies must be clean and free from flux and all contaminants. Use of no clean flux is not acceptable." AssemblyNote 35.992,190.616 r0 top
ZZ4 "These assemblies must comply with workmanship standards IPC-A-610 Class 2, unless otherwise specified." AssemblyNote 35.992,188.366 r0 top

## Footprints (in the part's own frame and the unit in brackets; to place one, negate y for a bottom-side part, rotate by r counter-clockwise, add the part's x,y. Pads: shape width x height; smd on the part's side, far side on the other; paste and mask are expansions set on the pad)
0402 [mm] "0402 from SM-752 data"
  rect 0.8x0.6 smd: 1(-0.6,0) 2(0.6,0)
  silkscreen extent -1.22,-0.52 1.22,0.52, body extent -0.55,-0.3 0.55,0.3, height 0.6
0603 [mm] "0603 from SM-752 data"
  rect 1x0.95 smd: 1(-0.8,0) 2(0.8,0)
  silkscreen extent -1.52,-0.69 1.52,0.69, body extent -0.87,-0.47 0.87,0.47, height 0.85
1206_190 [mm] "1206_190"
  rect 1.1x1.6 smd: 1(-1.7,0) 2(1.7,0)
  silkscreen extent -0.9,-1 0.9,1, body extent -1.75,-0.95 1.75,0.95, height 1.9
3216-18 [mm] "Medium density IPC, based on Kemet T495 dimensions"
  rect 1.8x1.25 smd: 1(-1.3,0) 2(1.3,0)
  silkscreen extent -2.49,-0.54 -2.49,0.54, body extent -1.7,-0.9 1.7,0.9, height 1.8
AssemblyNote [mm] "Assembly Note"
AssemblyNoteLabel [mm] "Assembly Note for PCB Labels"
Bumpon_SJ61A2 [mil] "3M Hemispherical Bumpon transparent"
  round 1 on Mech3: 0(0,0)
  silkscreen extent -192,-192 192,192, body extent -191,-192 193,192, height 250
DBV0005A_N [mm] "SOT23, 5-Leads, Body 2.9x1.6mm, Pitch 0.95mm, Lead Span 2.8mm, IPC Medium Density"
  rect 1.1x0.65 smd: 1(-1.2,0.95) 2(-1.2,0) 3(-1.2,-0.95) 4(1.2,-0.95) 5(1.2,0.95)
  silkscreen extent -0.25,-1.55 0.25,1.55, body extent -1.42,-1.46 1.42,1.46, height 1.08
DCK0006A_N [mm] "SOT23, 6-Leads, Body 2x1.3mm, Pitch 0.65mm, Lead Span 2.1mm, IPC Medium Density"
  rect 0.85x0.4 smd: 1(-0.95,0.65) 2(-0.95,0) 3(-0.95,-0.65) 4(0.95,-0.65) 5(0.95,0) 6(0.95,0.65)
  silkscreen extent -0.15,-1.1 0.15,1.1, body extent -1.14,-1 1.14,1, height 0.94
DRL0006A [mm] "SOTFL, 6-Flat Leads, Body 1.2x1.6x0.6mm, Pitch 0.5mm, TI recommended"
  rect 0.5x0.3 smd: 1(-0.75,0.5) 2(-0.75,0) 3(-0.75,-0.5) 4(0.75,-0.5) 5(0.75,0) 6(0.75,0.5)
  silkscreen extent -0.9,-0.95 0.9,0.95, body extent -0.85,-0.85 0.85,0.85, height 0.62
EPL3015 [mm] "COILCRAFT"
  rect 1.12x3.2 smd: 1(-1.04,0) 2(1.04,0)
  silkscreen extent -0.22,-1.65 0.23,1.68, body extent -1.6,-1.6 1.6,1.6, height 1.55
Epson_FC-12M [mm] "Epson"
  rect 0.7x1.4 smd: 1(-0.75,0) 2(0.75,0)
  body extent -1.05,-0.63 1.05,0.63, height 0.6
Fiducial10-20 [mm]
  round 1 smd mask+0.5: 1(0,0)
  Top Layer keep-out circle w1.178: c0,0 r0.5
Keystone_1902C [mil] "Hex Standoff, 4-40 threaded, nylon"
  round 1 on Mech4: 0(0,0)
  body extent -145,-126 146,126, height 501
Keystone_2462 [mm] "2x AA Battery Holder, Through-hole mount"
  rect 1.8x1.8 hole 1.27: 1(-13.59,7.495)
  round 1.8 hole 1.27: 2(-13.59,-7.495)
  round 4.05 hole 3.55: 3(13.59,-7.495) 4(13.59,7.495)
  silkscreen extent -16.18,-16.46 43.33,16.46, body extent -16.31,-16.46 43.4,16.46, height 16
LGA-12P [mm]
  rect 0.3x0.35 smd mask+0.05: 1(-0.75,-0.775) 2(-0.25,-0.775) 3(0.25,-0.775) 4(0.75,-0.775) 7(0.75,0.775) 8(0.25,0.775) 9(-0.25,0.775) 10(-0.75,0.775)
  rect 0.35x0.3 smd mask+0.05: 5(0.775,-0.25) 6(0.775,0.25) 11(-0.775,0.25) 12(-0.775,-0.25)
  silkscreen extent -1.8,-1.8 -1.29,-1.3
MF03A_N [mm] "SOT23, 3-Leads, Body 2.9x1.3mm, Pitch 0.95mm, Lead Span 2.4mm, IPC Medium Density"
  rect 1.3x0.6 smd: 1(-1.05,0.95) 2(-1.05,-0.95) 3(1.05,0)
  silkscreen extent -1.18,-1.5 0.7,1.92, body extent -0.7,-1.5 0.7,1.5, height 1.12
MF05A_L [mm] "SOT23, 5-Leads, Body 2.9x1.6mm, Pitch 0.95mm, Lead Span 2.8mm, IPC High Density"
  rect 0.9x0.65 smd: 1(-1.2,0.95) 2(-1.2,0) 3(-1.2,-0.95) 4(1.2,-0.95) 5(1.2,0.95)
  silkscreen extent -1.32,-1.55 0.35,1.95, body extent -0.9,-1.55 0.9,1.55, height 1.19
NORCOMP_182-009-213R171 [mm] "Connector; D Subminiature 9 Position; Right Angle"
  rect 1.8x1.8 hole 1.092: 1(-5.54,-10.92)
  round 1.8 hole 1.092: 2(-2.77,-10.92) 3(0,-10.92) 4(2.77,-10.92) 5(5.54,-10.92) 6(-4.155,-8.08) 7(-1.385,-8.08) 8(1.385,-8.08) 9(4.155,-8.08)
  round 4.76 hole 3.05: 10(-12.495,-9.5) 11(12.495,-9.5)
  silkscreen extent -15.4,-12.4 15.4,6, body extent -15.41,-12.98 15.41,6.1, height 12.55
"NY PMS 440 0025 PH" [mm] "4-40 nylon screw and mounting hole"
  round 8 hole 3.2: 1(0,0)
  body extent -3.3,-3.3 3.3,3.3, height 2.69
PBS0032A_N [mil]
  rect 60x9 smd: 1(-124,68.9) 2(-124,49.21) 3(-124,29.53) 4(-124,9.84) 5(-124,-9.84) 6(-124,-29.53) 7(-124,-49.21) 8(-124,-68.9) 17(124,-68.9) 18(124,-49.21) 19(124,-29.53) 20(124,-9.84) 21(124,9.84) 22(124,29.53) 23(124,49.21) 24(124,68.9)
  rect 9x60 smd: 9(-68.9,-124) 10(-49.21,-124) 11(-29.53,-124) 12(-9.84,-124) 13(9.84,-124) 14(29.53,-124) 15(49.21,-124) 16(68.9,-124) 25(68.9,124) 26(49.21,124) 27(29.53,124) 28(9.84,124) 29(-9.84,124) 30(-29.53,124) 31(-49.21,124) 32(-68.9,124)
  silkscreen extent -104,-100 100,104, body extent -140,-140 140,140, height 48
PogoPad [mil] "No Solder Paste"
  round 70 smd paste-35: 1(0,0)
PW0014A_M [mm] "TSOP, 14-Leads, Body 5x4.4mm, Pitch 0.65mm, IPC Low Density"
  oval 2x0.35 smd: 1(-2.9,1.95) 2(-2.9,1.3) 3(-2.9,0.65) 4(-2.9,0) 5(-2.9,-0.65) 6(-2.9,-1.3) 7(-2.9,-1.95) 8(2.9,-1.95) 9(2.9,-1.3) 10(2.9,-0.65) 11(2.9,0) 12(2.9,0.65) 13(2.9,1.3) 14(2.9,1.95)
  silkscreen extent -1.5,-2.55 1.53,2.55, body extent -3.21,-2.5 3.21,2.5, height 0.98
RGC0064B [mm]
  oval 0.6x0.24 smd mask+0.07: 1(-4.4,3.75) 2(-4.4,3.25) 3(-4.4,2.75) 4(-4.4,2.25) 5(-4.4,1.75) 6(-4.4,1.25) 7(-4.4,0.75) 8(-4.4,0.25) 9(-4.4,-0.25) 10(-4.4,-0.75) 11(-4.4,-1.25) 12(-4.4,-1.75) 13(-4.4,-2.25) 14(-4.4,-2.75) 15(-4.4,-3.25) 16(-4.4,-3.75) 33(4.4,-3.75) 34(4.4,-3.25) 35(4.4,-2.75) 36(4.4,-2.25) 37(4.4,-1.75) 38(4.4,-1.25) 39(4.4,-0.75) 40(4.4,-0.25) 41(4.4,0.25) 42(4.4,0.75) 43(4.4,1.25) 44(4.4,1.75) 45(4.4,2.25) 46(4.4,2.75) 47(4.4,3.25) 48(4.4,3.75)
  oval 0.24x0.6 smd mask+0.07: 17(-3.751,-4.4) 18(-3.251,-4.4) 19(-2.751,-4.4) 20(-2.251,-4.4) 21(-1.75,-4.4) 22(-1.25,-4.4) 23(-0.75,-4.4) 24(-0.25,-4.4) 25(0.25,-4.4) 26(0.75,-4.4) 27(1.25,-4.4) 28(1.75,-4.4) 29(2.251,-4.4) 30(2.751,-4.4) 31(3.251,-4.4) 32(3.751,-4.4) 49(3.751,4.4) 50(3.251,4.4) 51(2.751,4.4) 52(2.251,4.4) 53(1.75,4.4) 54(1.25,4.4) 55(0.75,4.4) 56(0.25,4.4) 57(-0.25,4.4) 58(-0.75,4.4) 59(-1.25,4.4) 60(-1.75,4.4) 61(-2.251,4.4) 62(-2.751,4.4) 63(-3.251,4.4) 64(-3.751,4.4)
  rect 4.25x4.25 smd paste-2.112: 65(0,0)
  silkscreen extent -5.1,-5.1 5.1,5.1, body extent -4.57,-4.57 4.57,4.57, height 1.01
SOD-523F [mm] "COMCHIP"
  rect 0.6x0.8 smd paste-0.05: 1(-0.85,0) 2(0.85,0)
  silkscreen extent -1.92,-0.87 1.1,0.88, body extent -0.9,-0.5 0.9,0.5, height 0.85
TC2030-MCP-NL [mil] "TAG-CONNECT"
  round 31 smd paste-16: 1(-25,-50) 2(25,-50) 3(-25,0) 4(25,0) 5(-25,50) 6(25,50)
  round 25 hole 39 unplated: MH1(0,-100) MH2(-40,100) MH3(40,100)
  silkscreen extent -122,-195 118,195
TI_Symbol_Overlay_Small [mm]
  silkscreen extent -2.3,-2.23 2.3,2.24
TP_25MIL-SMT#1 [mm]
  round 0.635 smd mask-0.064: 1(0,0)
TP_25MIL-SMT#2 [mm]
  round 0.535 smd mask-0.064: 1(0,0)
TP_SM_1MM#1 [mm] "1mm Test Point, SMT"
  rrect50% 10x18 smd paste-0.5: 1(0,0)
TP_SM_1MM#2 [mm] "1mm Test Point, SMT"
  rrect50% 18x10 smd paste-0.5: 1(0,0)
TP_SM_1MM#3 [mm] "1mm Test Point, SMT"
  round 1 smd paste-0.5: 1(0,0)
Wurth_61201420621 [mm] "Header, 2.54mm, 7x2, SMT"
  rect 4x0.9 smd: 1(-3,7.62) 2(3,7.62) 3(-3,5.08) 4(3,5.08) 5(-3,2.54) 6(3,2.54) 7(-3,0) 8(3,0) 9(-3,-2.54) 10(3,-2.54) 11(-3,-5.08) 12(3,-5.08) 13(-3,-7.62) 14(3,-7.62)
  silkscreen extent -4.75,-12.7 4.4,12.7, body extent -4.75,-12.7 4.75,12.7, height 10.43

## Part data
1 2 3 4 5 6 7 8 9 10 11 12 13 14 15: "Test Point, O.025\""
BT3 BT4: "2x AA Battery Holder, Through-hole mount"
C1 C2 C12: "CAP, TA, 10 µF, 10 V, +/- 10%, 3.4 ohm, SMD"
C3 C6 C7 C10 C11 C13 C14 C18 C19 C23 C24 C28 C36 C37 C40 C42 C48 C50 C52: "CAP, CERM, 0.1 µF, 10 V, +/- 10%, X5R, 0402"
C4 C27: "CAP, CERM, 1 µF, 6.3 V, +/- 20%, X5R, 0402"
C5 C20: "CAP, CERM, 2.2 µF, 16 V, +/- 10%, X5R, 0402"
C8 C26 C38: "CAP, CERM, 0.01 µF, 25 V, +/- 10%, X7R, 0402"
C9 C15: "CAP, TA, 1 µF, 16 V, +/- 10%, 9.3 ohm, SMD"
C16 C17 C21 C22 C34 C35: "CAP, CERM, 10 µF, 6.3 V, +/- 20%, X5R, 0402"
C25 C46 C49 C53 C54: "CAP, CERM, 2200 pF, 50 V, +/- 10%, X8R, 0402"
C29: "CAP, CERM, 0.47 µF, 6.3 V, +/- 10%, X5R, 0402"
C30: "CAP, CERM, 33 pF, 50 V, +/- 5%, C0G/NP0, 0603"
C31: "CAP, CERM, 39pF, 50V, +/-5%, C0G/NP0, 0402"
C32: "CAP, CERM, 100 µF, 10 V, +/- 20%, X5R, 1206_190"
C33: library part Capacitor, "CAP, CERM, xxxF, xxV, [TempCo], xx%, [PackageReference]"
C39 C41 C55 C56: "CAP, CERM, 1 µF, 16 V, +/- 10%, X5R, 0402"
C43: "CAP, CERM, 1500 pF, 50 V, +/- 10%, X7R, 0603"
C44 C57: "CAP, CERM, 3000 pF, 50 V, +/- 5%, C0G/NP0, 0603"
C45 C47: "CAP, CERM, 4700 pF, 10 V, +/- 10%, X5R, 0402"
C51: "CAP, CERM, 10 µF, 6.3 V, +/- 20%, X5R, 0603"
C58 C59: "CAP, CERM, 10 pF, 50 V, +/- 5%, C0G/NP0, 0603"
D1 D2: "Diode, Schottky, 35V, 0.1A, SOD-523F"
FID1 FID2 FID3: "Fiducial mark.  There is nothing to buy or mount."
H1 H2 H3 H4: "Bumpon, Hemisphere, 0.375 X 0.235, Black"
H5 H6 H7 H8: "Machine Screw, Round, #4-40 x 1/4, Nylon, Philips panhead"
H9 H10 H11 H12: "Standoff, Hex, 0.5\"L #4-40 Nylon"
J1: "Footprint for TC2030-MCP-NL"
J2: "Header(Shrouded), 2.54mm, 7x2, Gold, Black, SMT"
J3: "CONN DB9 FEMALE R/A SOLDER TH"
L1 L2 L3 L4 L5 L6: "Ferrite Bead, 600 ohm @ 100MHz, 0.2A, 0603"
L7: "Inductor, Shielded, Ferrite, 4.7uH, 1.2A, 0.14 ohm, SMD"
Logo1: library part TI_Logo, "Texas Instrument Corporate Signature"
R1 R2 R3 R4 R5 R7 R13 R14 R16 R19: "RES, 0, 5%, 0.063 W, 0402"
R6: "RES, 47 k, 5%, 0.063 W, 0402"
R8: "RES, 21.5 k, 1%, 0.063 W, 0402"
R9: "RES, 10.0 k, 1%, 0.063 W, 0402"
R10 R15 R20: "RES, 1.00 M, 1%, 0.1 W, 0402"
R11: "RES, 11.8 k, 1%, 0.063 W, 0402"
R12: "RES, 8.06 k, 1%, 0.063 W, 0402"
R17: "RES, 200 k, 1%, 0.1 W, 0402"
R18: "RES, 4.99 k, 1%, 0.063 W, 0402"
R21 R22: "RES, 100 k, 1%, 0.1 W, 0402"
R23 R30: "RES, 51.1 k, 1%, 0.063 W, 0402"
R24 R25 R28 R29: "RES, 10.0 M, 1%, 0.063 W, 0402"
R26 R27: "RES, 40.2 k, 1%, 0.063 W, 0402"
R31 R32: "RES, 3.3 k, 5%, 0.063 W, 0402"
TP1 TP2 TP3 TP4 TP5: library part TP_SM_1MM, "1mm Test Point, SMT"
TP6: library part PogoPad, "Pad for Pogo Pin Connector"
U1: "Single Output High PSRR LDO, 200 mA, Fixed 3 V Output, 2.7 to 5.5 V Input, 5-pin SOT-23 (DBV), -40 to 85 degC, Green (RoHS & no Sb/Br)"
U2: "Single Micropower Precision Op Amp"
U3: "Precision Micropower Shunt Voltage Reference, 3-pin SOT-23"
U4: library part RF430CL331H, "The Texas Instruments Dynamic NFC Interface Transponder RF430CL331H is an NFC Tag Type 4 device  that combines a wireless NFC interface and a wired SPI or I2C interface to connect the device to a host."
U5: "LOW INPUT VOLTAGE STEP-UP CONVERTER IN 6 PIN SC-70 PACKAGE, DCK0006A"
U6: library part BMA250, "14 bit, digital, triaxial acceleration sensor with intelligent on-chip motion triggered interrupt controller"
U7: "High-Accuracy, Low-Power, Digital Temperature Sensor With SMBus(TM)/Two-Wire Serial Interface, DRL0006A"
U8: "Low-Power, 2-Channel, 24-Bit Analog Front-End for Biopotential Measurement, PBS0032A"
U9: "Mixed-Signal Microcontrollers, RGC0064B"
Y1: "Crystal, 32.768kHz, 12.5pF, SMD"
ZZ1: library part AssemblyNoteLabel
ZZ2 ZZ3 ZZ4: library part AssemblyNote

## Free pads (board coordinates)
  round 0 hole 3.762 unplated: 0(86.665,88.062)

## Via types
v1: diameter 0.864, hole 0.406, Top Layer to Bottom Layer, 104 vias
v2: diameter 0.5, hole 0.2, Top Layer to Bottom Layer, 13 vias

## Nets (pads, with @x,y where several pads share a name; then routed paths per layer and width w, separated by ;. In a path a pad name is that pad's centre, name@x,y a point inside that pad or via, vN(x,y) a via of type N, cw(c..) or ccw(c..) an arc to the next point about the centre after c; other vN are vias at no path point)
3V: C3.1 C4.1 C35.1 R4.2 R5.2 R15.2 U1.1 U1.3 U5.4 | length 53.6
  Top Layer w0.254: U1.3@91.903,102.55 U1.3@91.981,102.628 ; 93.142,100.178 93.243,100.178 ; C3.1@93.425,102.55 C3.1@93.502,102.628 ; 95.418,106.02 95.418,106.061
  Top Layer w0.54: R15.2@91.77,104.496 95.418,104.496 ; U1.1@91.903,100.65 92.669,100.65 93.142,100.178 ; U1.3@91.903,102.55 C3.1@93.425,102.55 ; 93.243,100.178 96.596,100.178 97.104,100.686 97.104,101.702 94.656,104.15 95.418,104.496 ; C3.1@93.502,102.628 C4.1@94.772,102.628 94.772,104.034 ; U5.4@94.401,109.662 94.401,110.632 94.767,110.998 96.241,110.998 96.749,110.49 ; C35.1@94.605,105.41 95.418,105.41 ; 95.418,106.02 95.418,105.41 ; 95.418,106.061 96.037,106.68 96.037,107.696 96.342,108.001 96.342,110.084 96.749,110.49 ; v1(99.39,113.132) 96.749,110.49 ; v1(101.93,115.672) 104.724,115.672 111.516,122.463 R5.2@111.516,124.816 ; R4.2@111.496,126.365 111.516,126.346 R5.2@111.516,124.861 ; 95.418,104.496 95.418,105.41
  Bottom Layer w0.54: v1(99.39,113.132) v1(101.93,115.672)
ADS1292_DRDY: 9.1 U8.22 U9.16 | length 19.6
  Top Layer w0.254: U8.22@88.202,138.704 88.202,137.039 88.468,136.773 v1(88.468,136.754) ; U9.16@93.376,128.312 v1(94.758,128.312) 95.072,127.998 9.1@95.072,127.356
  Bottom Layer w0.254: v1(88.468,136.754) 88.468,134.602 92.412,130.658 ; 92.412,130.658 v1(94.758,128.312) 94.758,129.448 93.548,130.658 92.412,130.658
ADS1292_ELA: C52.1 J3.2 R30.1 TP4.1 | length 93.4
  Top Layer w1: R30.1@82.521,151.409 82.521,154.733 ; J3.2@86.282,160.454 86.284,157.302 ; C52.1@92.278,152.086 92.278,153.518 91.008,154.788 82.521,154.733 ; TP4.1@144.018,143.358 144.018,153.822 140.538,157.302 87.452,157.302 83.795,157.302 82.521,156.028 82.521,154.733
ADS1292_ERA: C48.1 J3.1 R23.1 TP3.1 | length 92.4
  Top Layer w0.54: R23.1@83.795,151.437 v1@83.795,153.67
  Top Layer w1: TP3.1@27.584,143.358 27.584,153.822 30.175,156.413 77.826,156.413 81.866,160.454 J3.1@83.512,160.454 ; v1(93.497,155.143) 93.548,155.092 C48.1@93.548,152.086
  Bottom Layer w0.54: v1@83.795,153.67 84.607,154.534
  Bottom Layer w1: J3.1@83.512,160.454 83.512,156.873 83.795,156.591 83.795,153.67 v1(83.795,153.314) ; 83.998,155.143 v1(93.497,155.143)
ADS1292_GPIO1: 6.1 U8.26 U9.14 | length 24.5
  Top Layer w0.254: U8.26@90.602,140.603 91.985,140.603 93.499,139.089 93.499,137.976 95.483,135.992 ; U9.14@93.376,127.312 94.1,127.312 95.822,125.59 v1@95.822,125.336 ; 6.1@94.056,131.674 94.927,131.674 v1(95.333,132.08) 95.489,132.236 95.489,135.992
  Bottom Layer w0.254: v1(95.333,132.08) 97.358,130.055 97.358,126.848 v1(95.834,125.324)
ADS1292_GPIO2: 7.1 U8.25 U9.25 | length 20.5
  Top Layer w0.254: U9.25@88.726,128.962 88.726,129.729 ; 88.725,129.73 88.725,131.626 89.941,132.842 94.513,132.842 95.072,133.401 95.072,135.839 93.045,137.866 93.045,138.8 91.742,140.103 U8.25@90.602,140.103 ; 88.725,131.166 7.1@90.246,131.166
ADS1292_IN1N: C46.1 R24.1 R25.2 U8.3 | length 12.8
  Top Layer w0.254: R24.1@88.052,152.202 88.722,152.202 ; U8.3@88.202,145.003 88.202,148.184 88.468,148.45 v1(88.468,148.946) ; 88.278,147.753 88.961,147.753 C46.1@89.646,148.438 ; v1(88.722,153.264) 88.722,152.202 ; R25.2@89.646,152.202 88.722,152.202
  Bottom Layer w0.254: v1(88.468,148.946) 88.468,150.932 88.722,151.186 v1(88.722,153.264)
ADS1292_IN1P: C54.1 R28.1 R29.2 U8.4 | length 9.1
  Top Layer w0.254: U8.4@87.702,145.003 87.702,149.246 88.163,149.708 C54.1@89.646,149.708 ; R28.1@88.052,150.932 88.849,150.932 ; 88.849,149.835 88.849,150.932 ; R29.2@89.646,150.932 88.849,150.932
ADS1292_IN2N: C44.1 R23.2 U8.5 | length 8.7
  Top Layer w0.254: C44.1@85.319,150.291 83.849,150.291 R23.2@83.795,150.237 83.795,149.447 84.15,149.092 85.034,149.092 85.319,148.807 87.202,146.924 U8.5@87.202,145.003
ADS1292_IN2P: C57.1 R30.2 U8.6 | length 9.5
  Top Layer w0.254: C57.1@80.997,150.263 82.467,150.263 R30.2@82.521,150.209 ; R30.2@82.467,150.209 82.467,149.359 83.188,148.638 84.846,148.638 86.702,146.782 U8.6@86.702,145.003
ADS1292_MAIN_CLKSEL: 14.1 U8.14 U9.32 | length 17.1
  Top Layer w0.254: U8.14@84.303,141.103 82.892,141.103 82.226,140.437 82.226,130.658 82.734,130.15 84.912,130.15 ; 14.1@84.912,130.912 84.912,130.15 ; U9.32@85.225,128.962 85.225,129.837 84.912,130.15
ADS1292_RESET: 8.1 U8.15 U9.31 | length 16.9
  Top Layer w0.254: 8.1@84.15,132.944 84.15,131.597 ; U8.15@84.303,140.603 84.283,140.583 83.188,140.583 82.68,140.075 82.68,132.128 83.211,131.597 84.15,131.597 ; U9.31@85.725,128.962 85.725,131.368 85.497,131.597 84.15,131.597
ADS1292_RESP_MODP/IN3N: R26.2 U8.32 | length 2.4
  Top Layer w0.254: U8.32@90.602,143.603 92.27,143.603 92.278,143.612 R26.2@92.278,144.328
ADS1292_RESP_MODP/IN3P: R27.2 TP6.1 U8.31 | length 13.4
  Top Layer w0.254: U8.31@90.602,143.103 92.324,143.103 R27.2@93.548,144.328 96.55,144.328 97.358,145.136 TP6.1@97.358,150.901
ADS1292_RLD: J3.4 R22.2 TP5.1 | length 3.2
  Top Layer w0.254: R22.2@102.022,147.168 103.708,147.168 v1(104.216,146.66)
  Bottom Layer w0.254: v1(104.216,146.66) 104.75,146.126
ADS1292_SPI_CS: 10.1 U8.18 U9.29 | length 14.1
  Top Layer w0.254: 84.242,135.23 10.1@85.42,135.23 ; 86.156,137.328 85.369,136.541 84.75,136.541 84.15,135.941 84.15,134.722 84.404,134.468 86.029,134.468 86.726,133.771 U9.29@86.726,128.962 ; 86.202,137.374 U8.18@86.202,138.704
ADS1292_SPI_DIN: 12.1 U8.19 U9.26 | length 17.3
  Top Layer w0.254: 12.1@80.848,135.23 80.848,135.992 81.102,136.246 v1(81.102,136.5) ; v1@86.702,136.766 U8.19@86.702,138.704 ; U9.26@88.226,128.962 88.226,132.143 v1(88.671,132.588)
  Bottom Layer w0.254: v1(81.102,136.5) v1(86.436,136.5) 86.436,134.823 v1(88.671,132.588)
ADS1292_SPI_DOUT: 11.1 U8.21 U9.27 | length 29.7
  Top Layer w0.254: U9.27@87.726,128.962 87.726,134.074 87.702,134.098 U8.21@87.702,138.704 87.702,140.052 v1(88.468,140.818) ; v1(98.882,147.93) 98.882,149.2 11.1@100.914,151.232
  Bottom Layer w0.254: v1(88.468,140.818) 92.532,144.882 95.834,144.882 v1(98.882,147.93)
ADS1292_SPI_SCLK: 13.1 U8.20 U9.28 | length 21.9
  Top Layer w0.254: 13.1@80.797,147.32 81.559,146.558 83.083,146.558 v1(83.591,146.05) ; v1(86.69,140.31) 87.198,139.802 87.198,133.96 87.226,133.932 U9.28@87.226,128.962
  Bottom Layer w0.254: v1(83.591,146.05) 83.591,143.408 v1(86.69,140.31)
ADS1292_START: 15.1 U8.16 U9.30 | length 15.2
  Top Layer w0.254: 83.134,137.77 15.1@83.896,137.77 ; U8.16@84.303,140.103 83.416,140.103 83.134,139.821 83.134,138.204 83.134,134.722 83.896,133.96 85.674,133.96 86.226,133.408 U9.30@86.226,128.962
ADS1292_VCAP1: C55.1 U8.11 | length 4.6
  Top Layer w0.254: C55.1@79.724,142.603 U8.11@84.303,142.603
ADS1292_VCAP2: C56.1 U8.27 | length 6.8
  Top Layer w0.254: U8.27@90.602,141.103 92.4,141.103 93.953,139.55 93.953,138.022 94.46,137.516 C56.1@94.98,137.516
ADS1292_VREFP: C50.1 C51.1 U8.9 | length 5.9
  Top Layer w0.254: C51.1@80.585,145.58 C51.1@80.289,145.58 80.397,145.472 C50.1@81.813,145.472 82.645,145.472 82.829,145.288 82.829,144.018 83.244,143.603 U8.9@84.303,143.603
ADS_AVCC: C22.1 C23.1 C24.1 C39.1 C40.1 L6.2 R8.2 R24.2 R28.2 U2.5 U8.12 | length 21.4
  Top Layer w0.254: U2.5@75.052,143.8 76.007,143.8 76.225,144.018 v1(76.225,144.78) ; v1(75.463,145.542) 75.512,145.493 76.685,145.493 77.292,146.101 R8.2@77.292,147.33 ; v1(77.241,136.906) 77.605,137.27 78.458,137.27 C23.1@78.516,137.212 ; v1(77.834,141.106) C39.1@79.786,141.106 ; L6.2@78.562,135.522 78.562,137.166 C23.1@78.516,137.212 ; v1(79.578,148.184) C24.1@79.578,150.378 ; C22.1@79.786,137.212 C23.1@78.516,137.212 ; C39.1@80.086,141.164 C40.1@81.356,141.164 82.296,142.103 U8.12@84.303,142.103 ; v1(86.852,149.362) R28.2@86.852,150.932 R24.2@86.852,152.202
ADS_AVSS: C22.2 C23.2 C24.2 C39.2 C40.2 C44.2 C50.2 C51.2 C55.2 C56.2 C57.2 J3.10 J3.11 R3.2 R9.1 R12.1 R25.1 R29.1 U2.2 U3.2 U8.10 U8.13 | length 43.8
  Top Layer w0.254: v1(66.961,123.489) R3.2@68.777,123.489 ; v1(71.566,142.85) U2.2@72.652,142.85 ; R12.1@74.707,148.117 73.736,149.088 73.736,151.74 74.432,152.436 77.684,152.436 79.512,152.436 ; v1@76.784,143.612 v1(77.038,143.612) 77.038,143.205 77.648,142.596 C55.2@78.516,142.596 ; v1(78.765,146.304) 78.765,144.272 79.057,143.98 C51.2@80.289,143.98 80.581,144.272 C50.2@81.813,144.272 81.813,143.51 82.22,143.104 82.829,143.104 U8.10@84.303,143.103 ; C24.2@79.578,151.578 v1(79.578,153.518) ; C22.2@79.786,138.412 78.516,138.412 78.516,139.906 79.786,139.906 80.952,139.906 C40.2@81.183,140.137 ; C57.2@80.997,151.863 v1(80.997,153.496) ; C40.2@81.356,139.964 81.356,140.068 82.65,141.362 ; 82.65,141.373 82.88,141.603 U8.13@84.303,141.603 ; C44.2@85.319,151.891 v1(85.319,153.416) ; R29.1@90.846,150.932 R25.1@90.846,152.202 v1(90.846,153.426) ; C56.2@96.18,137.516 96.18,136.916 v1(96.596,136.5)
  Top Layer w0.54: v1(102.946,135.484) R9.1@102.946,137.17
  other v1: 78.816,139.906
ADS_DVCC: C15.1 C19.1 C20.1 C21.1 C41.1 C42.1 L5.2 L6.1 U8.23 | length 24.7
  Top Layer w0.254: L6.1@78.562,133.972 78.816,133.972 v1(78.816,132.436) ; 88.468,135.484 88.468,134.376 88.722,134.122 C42.1@89.484,134.122 C41.1@90.754,134.122 C19.1@92.024,134.122 C20.1@93.294,134.122 ; 88.485,135.5 89.23,136.246 89.23,137.008 88.702,137.536 U8.23@88.702,138.704 ; C20.1@93.323,134.15 C20.1@93.294,134.122 ; v1(94.259,133.858) 94.259,133.896 94.034,134.122 C20.1@93.294,134.122 ; v1(96.596,132.944) C21.1@96.596,134.122 97.266,133.452 L5.2@98.59,133.452 98.59,134.176 99.644,135.23 99.644,139.294 98.882,140.056 C15.1@98.882,141.296
ANTENNA: D1.2 D2.2 R13.2 R14.2 | length 600.2
  Top Layer w0.4: v1(76.022,95.86) 76.784,96.622 97.612,96.622 97.612,73 75.26,73 75.26,97.13 98.12,97.13 98.12,72.492 74.752,72.492 74.752,97.638 98.628,97.638 98.628,71.984 74.193,71.984 74.193,98.044 75.006,98.857 75.006,103.631 75.562,104.055 76.653,104.055 ; v1(76.022,100.178) 76.022,101.702 76.632,102.311 83.388,102.311 83.718,102.641 D2.2@83.718,103.239 ; D1.2@76.653,106.379 76.653,104.055 ; R13.2@78.431,104.055 76.653,104.055 ; 79.955,102.311 R14.2@79.955,104.055
  Bottom Layer w0.4: 74.193,97.079 74.193,71.984 98.628,71.984 98.628,97.638 76.022,97.638 v1(76.022,100.178) ; 74.244,97.13 98.12,97.13 98.12,72.492 74.752,72.492 74.752,96.622 97.612,96.622 97.612,73 75.26,73 75.26,95.098 v1(76.022,95.86)
BMA_AVCC: C16.1 C37.1 L4.1 U6.7 | length 5.4
  Top Layer w0.254: C16.1@72.974,128.647 C37.1@74.244,128.647 ; U6.7@73.977,127.111 73.977,128.38 C37.1@74.244,128.647 ; L4.1@75.73,129.896 75.73,129.045 75.491,128.805 74.403,128.805 C37.1@74.244,128.647
BMA_DVCC: C17.1 C36.1 L3.2 L4.2 U6.1 U6.3 U6.11 | length 28.6
  Top Layer w0.254: U6.11@74.502,125.586 74.502,124.794 74.219,124.511 72.873,124.511 71.603,125.781 71.603,129.616 73.101,131.115 76.962,131.115 77.33,130.747 L4.2@77.33,129.896 77.33,129.096 78.308,128.118 L3.2@79.286,128.118 79.324,128.08 C17.1@79.324,126.224 C36.1@78.054,126.224 77.667,126.611 U6.3@75.527,126.611 ; U6.1@75.527,125.611 75.527,125.158 75.971,124.714 76.835,124.714 77.318,125.197 77.318,126.585
BMA_INT1: U6.5 U9.38 | length 11
  Top Layer w0.254: U6.5@75.002,127.136 75.002,127.657 75.137,127.792 v1(75.613,127.792) ; v1(81.102,126.848) 82.118,125.832 ; 82.138,125.812 U9.38@84.576,125.812
  Bottom Layer w0.254: v1(75.613,127.792) 76.581,127.792 77.6,126.774 78.146,126.774 78.219,126.848 v1(81.102,126.848)
BMA_INT2: U6.6 U9.33 | length 12.2
  Top Layer w0.254: U6.6@74.502,127.136 74.502,127.88 75.074,128.451 76.149,128.451 76.476,128.778 v1(76.556,128.778) ; v1(82.829,129.286) 82.829,128.676 83.194,128.312 U9.33@84.576,128.312
  Bottom Layer w0.254: v1(76.556,128.778) 82.321,128.778 v1(82.829,129.286)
